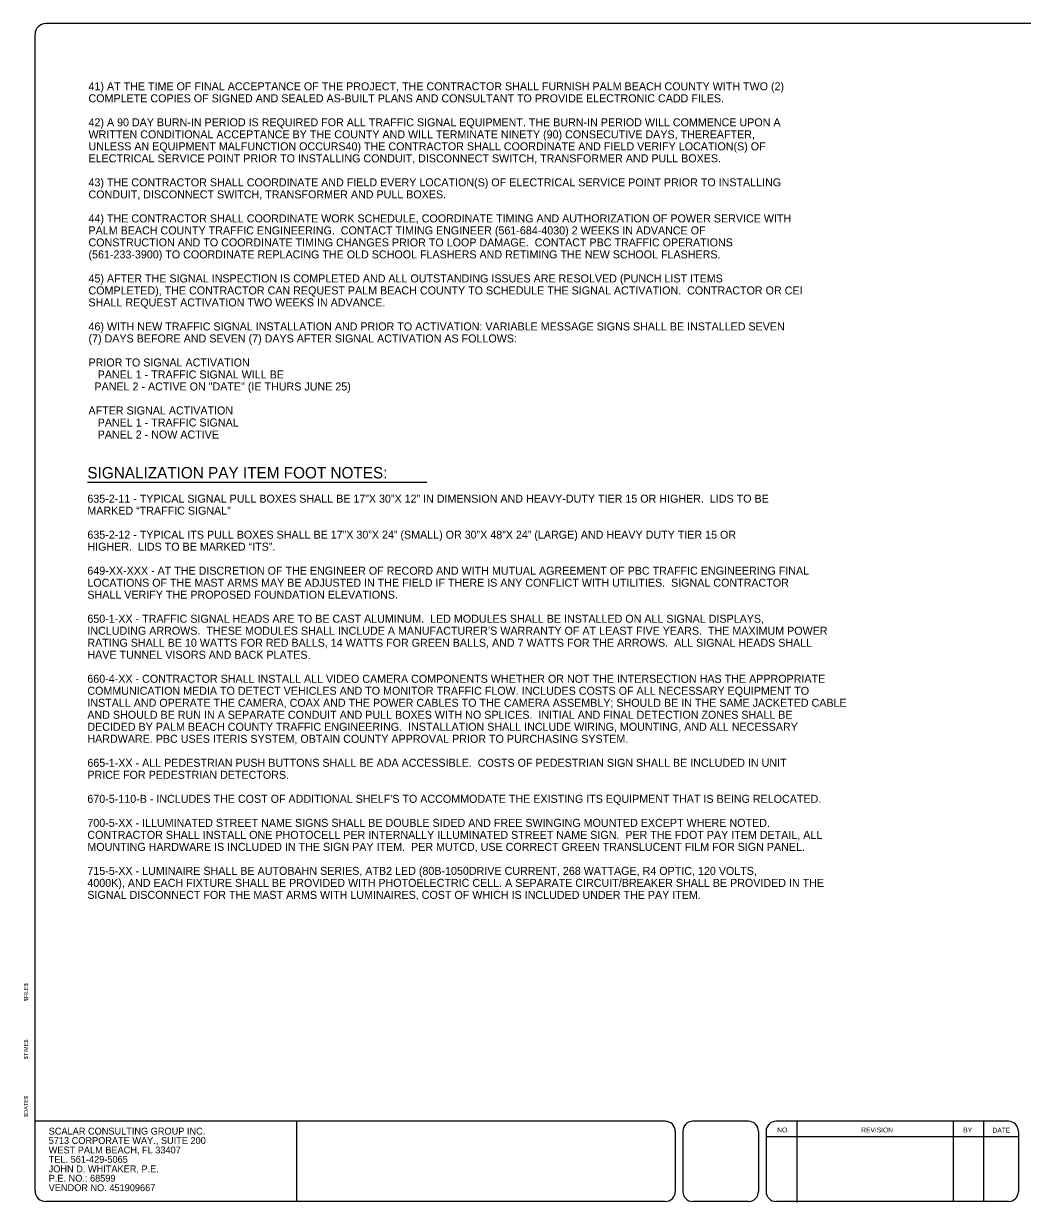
# Model space of a CAD drawing. Extents: x -1.6 to 33.4, y -12.7 to 10.9.
# Drawn here: x 17.87 to 26.6, y -12.68 to -2.37 of the extents above; entities that cross this region are included whole.
import ezdxf

# ---------------------------------------------------------------- set-up
doc = ezdxf.new("R2010")
doc.units = 0
doc.layers.add('Default', color=7, linetype='Continuous')
doc.layers.add('NonPlottingEle_dp', color=7, linetype='Continuous')

msp = doc.modelspace()

# ---------------------------------------------------------------- linework, layer by layer
at = {"layer": 'Default'}
for p, q in [((17.968, -12.582), (17.968, -2.468)), ((33.293, -2.374), (18.061, -2.374)), ((23.476, -11.974), (17.968, -11.974)), ((20.256, -12.676), (20.256, -11.974)), ((24.203, -11.974), (23.718, -11.974)), ((26.475, -11.974), (24.446, -11.974)), ((24.626, -11.978), (24.626, -12.684)), ((25.993, -11.978), (25.993, -12.675)), ((26.258, -11.978), (26.258, -12.675)), ((23.564, -12.062), (23.564, -12.587)), ((23.63, -12.062), (23.63, -12.587)), ((24.292, -12.062), (24.292, -12.587)), ((24.358, -12.062), (24.358, -12.587)), ((26.567, -12.11), (24.361, -12.11)), ((26.563, -12.062), (26.563, -12.587)), ((23.476, -12.676), (18.061, -12.676)), ((24.203, -12.676), (23.718, -12.676)), ((26.475, -12.676), (24.446, -12.676))]:
    msp.add_line(p, q, dxfattribs=at)
for centre, major_axis, start_param, end_param in [((18.061, -2.468), (0, -0.0935), 3.141593, 4.712389), ((23.476, -12.062), (0, 0.0882), 4.712389, 6.283185), ((23.718, -12.062), (0, 0.0882), 0, 1.570796), ((24.203, -12.062), (0, 0.0882), 4.712389, 6.283185), ((24.446, -12.062), (0, 0.0882), 0, 1.570796), ((26.475, -12.062), (0, 0.0882), 4.712389, 6.283185), ((18.061, -12.582), (0, -0.0935), 4.712389, 6.283185), ((23.476, -12.587), (0, 0.0882), 3.141593, 4.712389), ((23.718, -12.587), (0, -0.0882), 4.712389, 6.283185), ((24.203, -12.587), (0, 0.0882), 3.141593, 4.712389), ((24.446, -12.587), (0, -0.0882), 4.712389, 6.283185), ((26.475, -12.587), (0, 0.0882), 3.141593, 4.712389)]:
    msp.add_ellipse(centre, major_axis=major_axis, ratio=0.999927, start_param=start_param, end_param=end_param, dxfattribs=at)
at = {"layer": 'NonPlottingEle_dp'}
msp.add_line((18.425, -6.385), (21.391, -6.385), dxfattribs=at)

# ---------------------------------------------------------------- texts
at = {"layer": 'Default'}
for s, p in [('$FILE$', (17.906, -10.924)), ('$TIME$', (17.906, -11.431)), ('$DATE$', (17.906, -11.936))]:
    msp.add_text(s, height=0.0354, rotation=90, dxfattribs=at).set_placement(p)
for s, height, p in [('SCALAR CONSULTING GROUP INC.', 0.06, (18.087, -12.09)), ('NO.', 0.0421, (24.455, -12.071)), ('REVISION', 0.0421, (25.189, -12.071)), ('BY', 0.0421, (26.081, -12.071)), ('DATE', 0.0421, (26.337, -12.073)), ('5713 CORPORATE WAY., SUITE 200', 0.06, (18.087, -12.172)), ('WEST PALM BEACH, FL 33407', 0.06, (18.087, -12.255)), ('TEL. 561-429-5065', 0.06, (18.087, -12.337)), ('JOHN D. WHITAKER, P.E.', 0.06, (18.087, -12.42)), ('P.E. NO.: 68599', 0.06, (18.087, -12.502)), ('VENDOR NO. 451909667', 0.06, (18.087, -12.585))]:
    msp.add_text(s, height=height, dxfattribs=at).set_placement(p)
at = {"layer": 'NonPlottingEle_dp'}
for s, height, p in [('41) AT THE TIME OF FINAL ACCEPTANCE OF THE PROJECT, THE CONTRACTOR SHALL FURNISH PALM BEACH COUNTY WITH TWO (2) ', 0.07, (18.435, -2.958)), ('COMPLETE COPIES OF SIGNED AND SEALED AS-BUILT PLANS AND CONSULTANT TO PROVIDE ELECTRONIC CADD FILES.  ', 0.07, (18.435, -3.063)), ('42) A 90 DAY BURN-IN PERIOD IS REQUIRED FOR ALL TRAFFIC SIGNAL EQUIPMENT. THE BURN-IN PERIOD WILL COMMENCE UPON A ', 0.07, (18.435, -3.273)), ('WRITTEN CONDITIONAL ACCEPTANCE BY THE COUNTY AND WILL TERMINATE NINETY (90) CONSECUTIVE DAYS, THEREAFTER, ', 0.07, (18.435, -3.378)), ('UNLESS AN EQUIPMENT MALFUNCTION OCCURS40) THE CONTRACTOR SHALL COORDINATE AND FIELD VERIFY LOCATION(S) OF ', 0.07, (18.435, -3.483)), ('ELECTRICAL SERVICE POINT PRIOR TO INSTALLING CONDUIT, DISCONNECT SWITCH, TRANSFORMER AND PULL BOXES. ', 0.07, (18.435, -3.588)), ('43) THE CONTRACTOR SHALL COORDINATE AND FIELD EVERY LOCATION(S) OF ELECTRICAL SERVICE POINT PRIOR TO INSTALLING ', 0.07, (18.435, -3.798)), ('CONDUIT, DISCONNECT SWITCH, TRANSFORMER AND PULL BOXES.', 0.07, (18.435, -3.903)), ('44) THE CONTRACTOR SHALL COORDINATE WORK SCHEDULE, COORDINATE TIMING AND AUTHORIZATION OF POWER SERVICE WITH ', 0.07, (18.435, -4.113)), ('PALM BEACH COUNTY TRAFFIC ENGINEERING.  CONTACT TIMING ENGINEER (561-684-4030) 2 WEEKS IN ADVANCE OF ', 0.07, (18.435, -4.218)), ('CONSTRUCTION AND TO COORDINATE TIMING CHANGES PRIOR TO LOOP DAMAGE.  CONTACT PBC TRAFFIC OPERATIONS ', 0.07, (18.435, -4.323)), ('(561-233-3900) TO COORDINATE REPLACING THE OLD SCHOOL FLASHERS AND RETIMING THE NEW SCHOOL FLASHERS. ', 0.07, (18.435, -4.428)), ('45) AFTER THE SIGNAL INSPECTION IS COMPLETED AND ALL OUTSTANDING ISSUES ARE RESOLVED (PUNCH LIST ITEMS ', 0.07, (18.435, -4.638)), ('COMPLETED), THE CONTRACTOR CAN REQUEST PALM BEACH COUNTY TO SCHEDULE THE SIGNAL ACTIVATION.  CONTRACTOR OR CEI ', 0.07, (18.435, -4.743)), ('SHALL REQUEST ACTIVATION TWO WEEKS IN ADVANCE.', 0.07, (18.435, -4.848)), ('46) WITH NEW TRAFFIC SIGNAL INSTALLATION AND PRIOR TO ACTIVATION: VARIABLE MESSAGE SIGNS SHALL BE INSTALLED SEVEN ', 0.07, (18.435, -5.058)), ('(7) DAYS BEFORE AND SEVEN (7) DAYS AFTER SIGNAL ACTIVATION AS FOLLOWS:    ', 0.07, (18.435, -5.163)), ('PRIOR TO SIGNAL ACTIVATION', 0.07, (18.435, -5.373)), ('PANEL 1 - TRAFFIC SIGNAL WILL BE   ', 0.07, (18.515, -5.478)), ('  PANEL 2 - ACTIVE ON "DATE" (IE THURS JUNE 25)', 0.07, (18.435, -5.583)), ('AFTER SIGNAL ACTIVATION ', 0.07, (18.435, -5.793)), ('PANEL 1 - TRAFFIC SIGNAL       ', 0.07, (18.515, -5.898)), ('PANEL 2 - NOW ACTIVE', 0.07, (18.515, -6.003)), ('SIGNALIZATION PAY ITEM FOOT NOTES:', 0.1, (18.425, -6.352)), ('635-2-11 - TYPICAL SIGNAL PULL BOXES SHALL BE 17”X 30”X 12” IN DIMENSION AND HEAVY-DUTY TIER 15 OR HIGHER.  LIDS TO BE ', 0.07, (18.425, -6.564)), ('MARKED “TRAFFIC SIGNAL”', 0.07, (18.425, -6.669)), ('635-2-12 - TYPICAL ITS PULL BOXES SHALL BE 17”X 30”X 24” (SMALL) OR 30”X 48”X 24” (LARGE) AND HEAVY DUTY TIER 15 OR ', 0.07, (18.425, -6.879)), ('HIGHER.  LIDS TO BE MARKED “ITS”.  ', 0.07, (18.425, -6.984)), ('649-XX-XXX - AT THE DISCRETION OF THE ENGINEER OF RECORD AND WITH MUTUAL AGREEMENT OF PBC TRAFFIC ENGINEERING FINAL ', 0.07, (18.425, -7.194)), ('LOCATIONS OF THE MAST ARMS MAY BE ADJUSTED IN THE FIELD IF THERE IS ANY CONFLICT WITH UTILITIES.  SIGNAL CONTRACTOR ', 0.07, (18.425, -7.299)), ('SHALL VERIFY THE PROPOSED FOUNDATION ELEVATIONS.   ', 0.07, (18.425, -7.404)), ('650-1-XX - TRAFFIC SIGNAL HEADS ARE TO BE CAST ALUMINUM.  LED MODULES SHALL BE INSTALLED ON ALL SIGNAL DISPLAYS, ', 0.07, (18.425, -7.614)), ('INCLUDING ARROWS.  THESE MODULES SHALL INCLUDE A MANUFACTURER’S WARRANTY OF AT LEAST FIVE YEARS.  THE MAXIMUM POWER ', 0.07, (18.425, -7.719)), ('RATING SHALL BE 10 WATTS FOR RED BALLS, 14 WATTS FOR GREEN BALLS, AND 7 WATTS FOR THE ARROWS.  ALL SIGNAL HEADS SHALL ', 0.07, (18.425, -7.824)), ('HAVE TUNNEL VISORS AND BACK PLATES.  ', 0.07, (18.425, -7.929)), ('660-4-XX - CONTRACTOR SHALL INSTALL ALL VIDEO CAMERA COMPONENTS WHETHER OR NOT THE INTERSECTION HAS THE APPROPRIATE ', 0.07, (18.425, -8.139)), ('COMMUNICATION MEDIA TO DETECT VEHICLES AND TO MONITOR TRAFFIC FLOW. INCLUDES COSTS OF ALL NECESSARY EQUIPMENT TO ', 0.07, (18.425, -8.244)), ('INSTALL AND OPERATE THE CAMERA, COAX AND THE POWER CABLES TO THE CAMERA ASSEMBLY; SHOULD BE IN THE SAME JACKETED CABLE ', 0.07, (18.425, -8.349)), ('AND SHOULD BE RUN IN A SEPARATE CONDUIT AND PULL BOXES WITH NO SPLICES.  INITIAL AND FINAL DETECTION ZONES SHALL BE ', 0.07, (18.425, -8.454)), ('DECIDED BY PALM BEACH COUNTY TRAFFIC ENGINEERING.  INSTALLATION SHALL INCLUDE WIRING, MOUNTING, AND ALL NECESSARY ', 0.07, (18.425, -8.559)), ('HARDWARE. PBC USES ITERIS SYSTEM, OBTAIN COUNTY APPROVAL PRIOR TO PURCHASING SYSTEM. ', 0.07, (18.425, -8.664)), ('665-1-XX - ALL PEDESTRIAN PUSH BUTTONS SHALL BE ADA ACCESSIBLE.  COSTS OF PEDESTRIAN SIGN SHALL BE INCLUDED IN UNIT ', 0.07, (18.425, -8.874)), ('PRICE FOR PEDESTRIAN DETECTORS.   ', 0.07, (18.425, -8.979)), ("670-5-110-B - INCLUDES THE COST OF ADDITIONAL SHELF'S TO ACCOMMODATE THE EXISTING ITS EQUIPMENT THAT IS BEING RELOCATED.", 0.07, (18.425, -9.189)), ('700-5-XX - ILLUMINATED STREET NAME SIGNS SHALL BE DOUBLE SIDED AND FREE SWINGING MOUNTED EXCEPT WHERE NOTED.  ', 0.07, (18.425, -9.399)), ('CONTRACTOR SHALL INSTALL ONE PHOTOCELL PER INTERNALLY ILLUMINATED STREET NAME SIGN.  PER THE FDOT PAY ITEM DETAIL, ALL ', 0.07, (18.425, -9.504)), ('MOUNTING HARDWARE IS INCLUDED IN THE SIGN PAY ITEM.  PER MUTCD, USE CORRECT GREEN TRANSLUCENT FILM FOR SIGN PANEL. ', 0.07, (18.425, -9.609)), ('715-5-XX - LUMINAIRE SHALL BE AUTOBAHN SERIES, ATB2 LED (80B-1050DRIVE CURRENT, 268 WATTAGE, R4 OPTIC, 120 VOLTS, ', 0.07, (18.425, -9.819)), ('4000K), AND EACH FIXTURE SHALL BE PROVIDED WITH PHOTOELECTRIC CELL. A SEPARATE CIRCUIT/BREAKER SHALL BE PROVIDED IN THE ', 0.07, (18.425, -9.924)), ('SIGNAL DISCONNECT FOR THE MAST ARMS WITH LUMINAIRES, COST OF WHICH IS INCLUDED UNDER THE PAY ITEM.  ', 0.07, (18.425, -10.029))]:
    msp.add_text(s, height=height, dxfattribs=at).set_placement(p)

doc.saveas('drawing.dxf')
